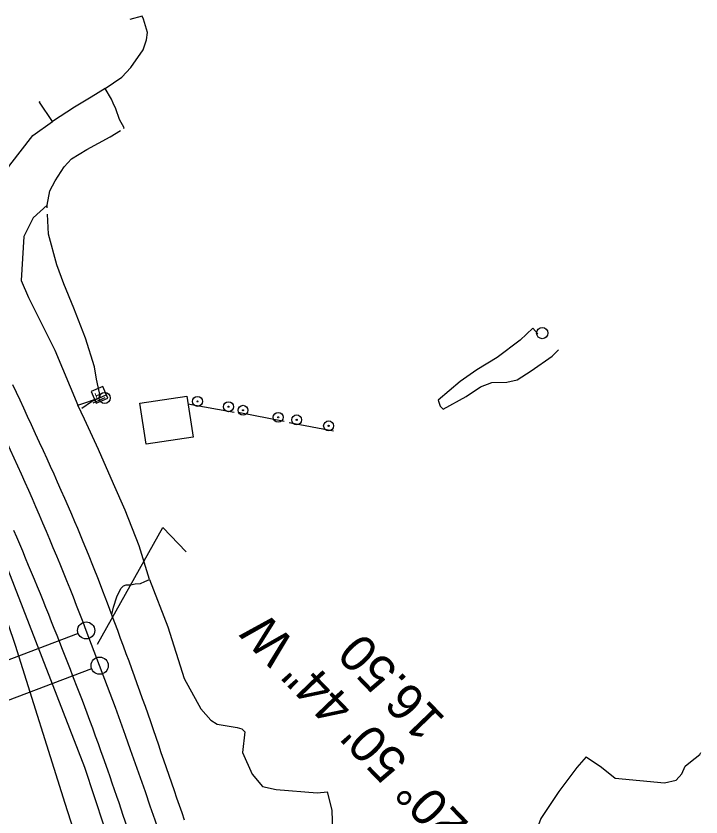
# Model space of a CAD drawing. Extents: x 471894 to 476235, y 503501 to 507878.
# Drawn here: x 474361.6 to 474661.7, y 505090.4 to 505441.4 of the extents above; entities that cross this region are included whole.
import ezdxf

# ---------------------------------------------------------------- set-up
doc = ezdxf.new("R2010")
doc.units = 0
for name, color, linetype in [('CTL Secondary Horizontal and Vertical Leader', 7, 'Continuous'), ('Exist Building Metal Canopy', 7, 'Continuous'), ('Exist Horizontal Alignment', 7, 'Continuous'), ('Exist Horizontal Alignment Direction Label', 7, 'Continuous'), ('Exist Other Culture Fence Line', 7, 'Continuous'), ('Exist Other Culture Sign', 7, 'Continuous'), ('Exist Other Culture Sign Post CELL', 7, 'Continuous'), ('Exist Roads EOP', 7, 'Continuous'), ('Exist Roads EOP Other', 7, 'Continuous'), ('Exist Roads Soil', 7, 'Continuous'), ('Exist Utilities Other Pole CELL', 7, 'Continuous'), ('Exist Utilities Power Pole CELL', 7, 'Continuous'), ('Exist Utilities Telephone Pedestal CELL', 7, 'Continuous'), ('Exist Vegetation Woods Line', 7, 'Continuous')]:
    doc.layers.add(name, color=color, linetype=linetype)

msp = doc.modelspace()

# ---------------------------------------------------------------- linework, layer by layer
at = {"layer": 'CTL Secondary Horizontal and Vertical Leader'}
msp.add_lwpolyline([(474397.31, 505166.19), (474425.93, 505217.27), (474436.22, 505206.58)], dxfattribs=at)
at = {"layer": 'Exist Building Metal Canopy'}
msp.add_lwpolyline([(474415.89, 505271.73), (474436.5, 505274.9), (474439.26, 505256.92), (474418.65, 505253.75)], close=True, dxfattribs=at)
at = {"layer": 'Exist Horizontal Alignment'}
for p, q in [((474398.24, 505156.74), (474392.36, 505172.16)), ((474388.86, 505170.83), (474237.56, 505113.21)), ((474394.73, 505155.4), (474289.39, 505115.29))]:
    msp.add_line(p, q, dxfattribs=at)
for centre in [(474392.36, 505172.16), (474398.24, 505156.74)]:
    msp.add_circle(centre, 3.75, dxfattribs=at)
for centre, radius, start, end in [((473181.76, 504711.19), 1295.4, 20.84556, 26.36313), ((472660.82, 504495.17), 1859.11, 14.39186, 20.84556)]:
    msp.add_arc(centre, radius, start, end, dxfattribs=at)
at = {"layer": 'Exist Other Culture Fence Line'}
msp.add_lwpolyline([(474390.39, 505269.58), (474394.66, 505272.52), (474401.1, 505275.45)], dxfattribs=at)
at = {"layer": 'Exist Other Culture Sign'}
for p, q in [((474436.82, 505271.42), (474457.14, 505267.77)), ((474458.96, 505267.84), (474479.02, 505263.9)), ((474481.22, 505263.34), (474500.71, 505259.63))]:
    msp.add_line(p, q, dxfattribs=at)
at = {"layer": 'Exist Other Culture Sign Post CELL'}
for centre, radius in [((474441.11, 505272.54), 2.18), ((474441.11, 505272.54), 0.24), ((474454.7, 505270.21), 2.18), ((474454.7, 505270.21), 0.24), ((474461.06, 505268.65), 2.18), ((474461.06, 505268.65), 0.24), ((474476.48, 505265.56), 2.18), ((474484.57, 505264.45), 2.18), ((474476.48, 505265.56), 0.24), ((474484.57, 505264.45), 0.24), ((474498.57, 505261.81), 2.18), ((474498.57, 505261.81), 0.24)]:
    msp.add_circle(centre, radius, dxfattribs=at)
at = {"layer": 'Exist Roads EOP'}
for points in [[(474360.06, 505279.98), (474361.63, 505276.6), (474363.22, 505273.18), (474364.84, 505269.68), (474366.51, 505266.08), (474368.24, 505262.36), (474370.03, 505258.54), (474371.8, 505254.73), (474373.5, 505251.05), (474375.11, 505247.51), (474376.64, 505244.11), (474378.14, 505240.73), (474379.68, 505237.26), (474381.24, 505233.7), (474382.84, 505230.06), (474384.41, 505226.48), (474385.87, 505223.09), (474387.23, 505219.9), (474388.49, 505216.91), (474389.69, 505214.03), (474390.87, 505211.18), (474392.04, 505208.35), (474393.2, 505205.55), (474395.43, 505200.05), (474397.53, 505194.69), (474399.55, 505189.46), (474401.51, 505184.33), (474403.6, 505178.78), (474404.77, 505175.65), (474406.02, 505172.28), (474407.29, 505168.82), (474408.54, 505165.41), (474409.77, 505162.07), (474410.98, 505158.77), (474412.18, 505155.51), (474413.37, 505152.23), (474414.57, 505148.95), (474415.75, 505145.67), (474416.94, 505142.36), (474418.12, 505139.02), (474419.31, 505135.64), (474420.49, 505132.23), (474421.66, 505128.81), (474422.82, 505125.42), (474423.96, 505122.06), (474425.09, 505118.72), (474426.22, 505115.4), (474427.36, 505112.06), (474428.52, 505108.71), (474429.69, 505105.35), (474430.85, 505102.02), (474431.99, 505098.74), (474433.1, 505095.52), (474434.19, 505092.37), (474435.27, 505089.19)], [(474410.25, 505086.11), (474408.61, 505091.02), (474406.73, 505096.55), (474405.76, 505099.4), (474404.78, 505102.27), (474403.8, 505105.17), (474402.8, 505108.07), (474401.81, 505110.94), (474399.82, 505116.56), (474398.79, 505119.43), (474397.68, 505122.51), (474396.5, 505125.79), (474395.24, 505129.28), (474393.99, 505132.73), (474392.81, 505135.91), (474390.7, 505141.45), (474388.68, 505146.63), (474386.54, 505152.18), (474385.42, 505155.06), (474384.29, 505157.97), (474383.14, 505160.91), (474381.97, 505163.88), (474380.79, 505166.87), (474379.6, 505169.89), (474378.39, 505172.94), (474377.18, 505176), (474375.95, 505179.08), (474374.73, 505182.15), (474373.5, 505185.21), (474372.27, 505188.27), (474371.02, 505191.33), (474369.75, 505194.42), (474368.46, 505197.54), (474367.15, 505200.69), (474365.83, 505203.83), (474364.53, 505206.92), (474363.23, 505209.97), (474361.95, 505212.97), (474360.68, 505215.95)]]:
    msp.add_lwpolyline(points, dxfattribs=at)
at = {"layer": 'Exist Roads EOP Other'}
for points in [[(474408.65, 505392.14), (474409, 505392.37), (474406.89, 505396.03), (474405.27, 505400.75), (474404.23, 505403.26), (474403.37, 505404.97), (474400.64, 505409.61), (474394.49, 505405.85), (474387.23, 505401.43), (474377.53, 505395.2)], [(474344.12, 505346.75), (474345.27, 505352.15), (474349.48, 505362.68), (474358.95, 505376.1), (474368.94, 505389), (474377.53, 505395.2)], [(474375.26, 505357.35), (474375.21, 505358.54), (474376.38, 505364.81), (474378.82, 505369.23), (474382.66, 505375.29), (474385.97, 505378.82), (474392.69, 505382.92), (474402.88, 505388.48), (474407.35, 505391.32)], [(474375.21, 505358.54), (474369.13, 505352.99), (474365.07, 505344.87), (474363.87, 505325.47), (474367.03, 505318.1), (474378.6, 505294.94), (474388.71, 505270.88)], [(474416.14, 505192.8), (474418.11, 505193.62), (474420.14, 505194.43), (474415.57, 505209.29), (474409.36, 505224.91), (474404.29, 505236.39), (474397.73, 505251.47), (474391.62, 505264.8), (474388.71, 505270.88)], [(474403.54, 505179.21), (474404.33, 505182.35), (474405.75, 505186.94), (474407.48, 505190.55), (474408.73, 505191.75), (474409.8, 505192.16), (474411.73, 505192.19), (474413.85, 505192.59), (474416.14, 505192.8)]]:
    msp.add_lwpolyline(points, dxfattribs=at)
at = {"layer": 'Exist Roads Soil'}
msp.add_line((474416.81, 505441.43), (474411.51, 505439.92), dxfattribs=at)
for points in [[(474400.64, 505409.61), (474408, 505414.66), (474411.98, 505418.93), (474417.38, 505426.67), (474418.81, 505431.02), (474419.25, 505434.26), (474417.52, 505440.07), (474416.81, 505441.43)], [(474377.53, 505395.2), (474371.95, 505403.61), (474372, 505404.1)], [(474389.1, 505271.01), (474398.57, 505274.23), (474396.85, 505282.3), (474396.01, 505287.72), (474392.11, 505300.23), (474386.87, 505313.39), (474382.5, 505324.09), (474379.5, 505332.37), (474375.77, 505345.9), (474375.38, 505354.59)], [(474590.27, 505302.16), (474588.07, 505304.67), (474582.51, 505299.33), (474572.33, 505291.8), (474563.43, 505286.42), (474556.21, 505281.21), (474546.62, 505273.07), (474547.47, 505270.4), (474548.68, 505269.09), (474558.75, 505274.68), (474565.04, 505278.86), (474570.12, 505280.84), (474576.65, 505280.94), (474581.12, 505281.93), (474587.33, 505285.92), (474596.49, 505292.41), (474599.28, 505295.07)], [(474420.14, 505194.43), (474428.05, 505173.7), (474435.3, 505151.09), (474442.51, 505137.84), (474447.03, 505132.86), (474449.72, 505131.07), (474458.49, 505129.65), (474460.59, 505129.1), (474461.81, 505127.76), (474460.8, 505118.7), (474465.09, 505109.11), (474469.59, 505103.83), (474475.65, 505102.44), (474493.52, 505100.99), (474498.05, 505101.43)], [(474611.33, 505116.7), (474607.28, 505112.11), (474599.48, 505101.64), (474591.47, 505089.73), (474589.24, 505083.45), (474587.74, 505077.11), (474583.9, 505058.82), (474583.19, 505045.5), (474584.96, 505031.25), (474584.16, 505012.87), (474582.32, 505002.42), (474581.02, 505001.75), (474579.59, 505002.06), (474560.08, 505000.5), (474558.11, 504999.94), (474556.47, 504997.04), (474556.13, 504991.52), (474555.56, 504979.93), (474556.78, 504968.57), (474556.68, 504962.41), (474556.79, 504957.15), (474557.93, 504950.93), (474561.56, 504939.38), (474569.29, 504916.1)], [(474611.33, 505116.7), (474618.04, 505112.23), (474624.12, 505107.45), (474645.64, 505105.35), (474650.78, 505106.59), (474653.35, 505109.26), (474654.77, 505112.64), (474657.07, 505114.62), (474661.12, 505117.77), (474661.69, 505118.63)], [(474562.13, 504900.47), (474558.05, 504918.25), (474552.88, 504939.87), (474549.4, 504953.17), (474547.37, 504960.35), (474536.82, 504980.92), (474525.48, 504996.52), (474518.84, 505003.91), (474508.25, 505024.72), (474502.99, 505042.57), (474500.31, 505061.24), (474500.56, 505078.84), (474500.07, 505093.34), (474498.05, 505101.43)]]:
    msp.add_lwpolyline(points, dxfattribs=at)
at = {"layer": 'Exist Utilities Other Pole CELL'}
msp.add_circle((474592.16, 505302.47), 2.46, dxfattribs=at)
at = {"layer": 'Exist Utilities Power Pole CELL'}
for q in [(474395.33, 505271.76), (474400.46, 505274.05)]:
    msp.add_line((474400.46, 505274.05), q, dxfattribs=at)
msp.add_circle((474400.46, 505274.05), 2.45, dxfattribs=at)
at = {"layer": 'Exist Utilities Telephone Pedestal CELL'}
msp.add_line((474398.2, 505275.31), (474398.2, 505275.31), dxfattribs=at)
msp.add_lwpolyline([(474401.87, 505273.93), (474399.67, 505279.07), (474394.52, 505276.86), (474396.73, 505271.72), (474401.87, 505273.93)], dxfattribs=at)
at = {"layer": 'Exist Vegetation Woods Line'}
msp.add_lwpolyline([(474333.63, 505261.37), (474391.56, 505112.22), (474416.96, 505035.11), (474404.23, 505030.66), (474383.08, 505096.38), (474361.36, 505165.52), (474344.78, 505214.38), (474331, 505244.92), (474311.95, 505251.22), (474316.11, 505264.81), (474333.63, 505261.37)], dxfattribs=at)

# ---------------------------------------------------------------- texts
at = {"layer": 'Exist Horizontal Alignment Direction Label'}
for s, p in [('N 20%%d 50\' 44" W', (474575.34, 505072.11)), ('16.50', (474550.24, 505133.36))]:
    msp.add_text(s, height=16, rotation=133.8986, dxfattribs=at).set_placement(p)
at = {"layer": 'Exist Utilities Telephone Pedestal CELL'}
msp.add_text('T', height=3.42, rotation=113.2294, dxfattribs=at).set_placement((474400.22, 505274.95))

doc.saveas('drawing.dxf')
